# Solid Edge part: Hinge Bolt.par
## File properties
Author: m_hel
Template: iso metric part.par
Last saved by: m_hel
Revision: 3
Application: Solid Edge
Accuracy: 0,990
Username: m_hel
Material: Chrome
Face Style: Chrome
Fill Style: Normal
Virtual Style: Normal
Grouping: Uncategorized
LibraryName: Custom Materials
Coef. of Thermal Exp: 0.0
Thermal Conductivity: 0.0
Specific Heat: 0.0
Modulus of Elasticity: 0.0
Poisson's Ratio: 0.0
Yield Stress: 0.0
Ultimate Stress: 0.0
Elongation: 0.0
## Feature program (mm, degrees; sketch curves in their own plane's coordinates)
sketch for "unnamed Protrusion 1" plane through (0, 0, 0) normal (1, 0, 0) x-axis (0, 1, 0)
  circle centre (0, 0) radius 5
extrude "unnamed Protrusion 1" add finite 42 symmetric
sketch for "ExtrudedProtrusion_2" plane through (21, 0, 0) normal (1, 0, 0) x-axis (0, 1, 0)
  circle centre (0, 0) radius 6.5
extrude "ExtrudedProtrusion_2" add finite 4 along +normal
mirror "unnamed Mirror 1" of "ExtrudedProtrusion_2" about plane through (0, 0, 0) normal (1, 0, 0)
extrude "unnamed Protrusion 2" add finite 4
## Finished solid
Body 1: solid body, 7 faces, 6 edges, 0 vertices.
  Faces by surface: plane 4, cylinder 3
  Edges by curve: circle 6
Bounding box of the edges (mm): 50.000 x 13.000 x 13.000, from (-25, -6.5, -6.5) to (25, 6.5, 6.5).
Cylindrical faces by radius (mm): R5 x1, R6.5 x2
Planar faces by outward normal: +x 2, -x 2
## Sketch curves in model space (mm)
circle centre (21, 0, 0) radius 6.5
circle centre (0, 0, 0) radius 5
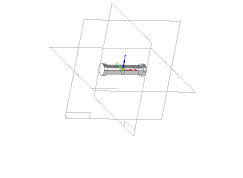
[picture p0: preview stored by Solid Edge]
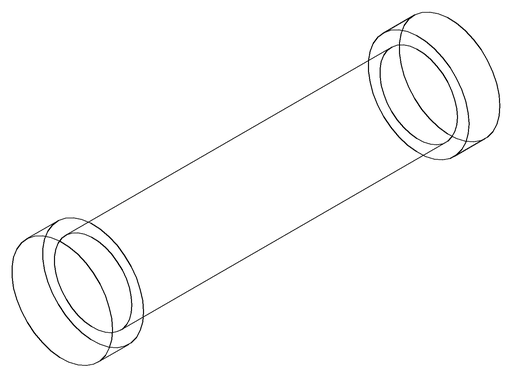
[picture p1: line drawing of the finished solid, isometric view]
